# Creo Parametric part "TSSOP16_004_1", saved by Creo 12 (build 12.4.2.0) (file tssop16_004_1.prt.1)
Units: Custom; MM, KILOGRAM, SECS

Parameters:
  PTC_WM_ITERATION = "0"
  PTC_WM_VERSION = "-.0"
  PTC_WM_LIFECYCLE_STATE = "In Work"
  PTC_WM_LIFECYCLE = "MO_CADDocument"
  PTC_WM_CREATED_BY = "Maximilian Roepper (Z0017RMS: MO)"
  PTC_WM_CREATED_ON = "18-Sep-26 11:36:42 AM"
  PTC_WM_MODIFIED_BY = "Maximilian Roepper (Z0017RMS: MO)"
  PTC_WM_MODIFIED_ON = "18-Sep-26 11:36:46 AM"
  PDMLINKNUMBER = "PDM000071454778"
  PTC_WM_NAME = "tssop16_004_1.prt"
  PTC_WM_NUMBER = "PDM000071454778"

Other parameters: WEIGHT, WEIGHT_FACTOR, WEIGHT_ADD, _MASS_TEMP, _DIFF_TEMP, MC_ERRORS, SUPPLIER

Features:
  1. coordinate system
  2. datum plane "PRT_YZ"
  3. datum plane "PRT_XY"
  4. datum plane "PRT_XZ"
  5. coordinate system
  6. datum axis
  7. datum axis
  8. datum axis
  9. coordinate system
  10. imported feature

Other named items: PRT, SIEMENS_MO, DRW_VIEW_ORG, PRT_X, PRT_Y, PRT_Z, CS0, ROUGH_GROB

Layers: 00_STD_CSYS-KSYS, 01_STD_PLANES-EBENEN, 02_STD_AXES-ACHSEN, 03_STD_CSYS-KSYS, 24_IMPORT_FEAT-IMPORT_KE

Surfaces: 14 plane, 8 cylinder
